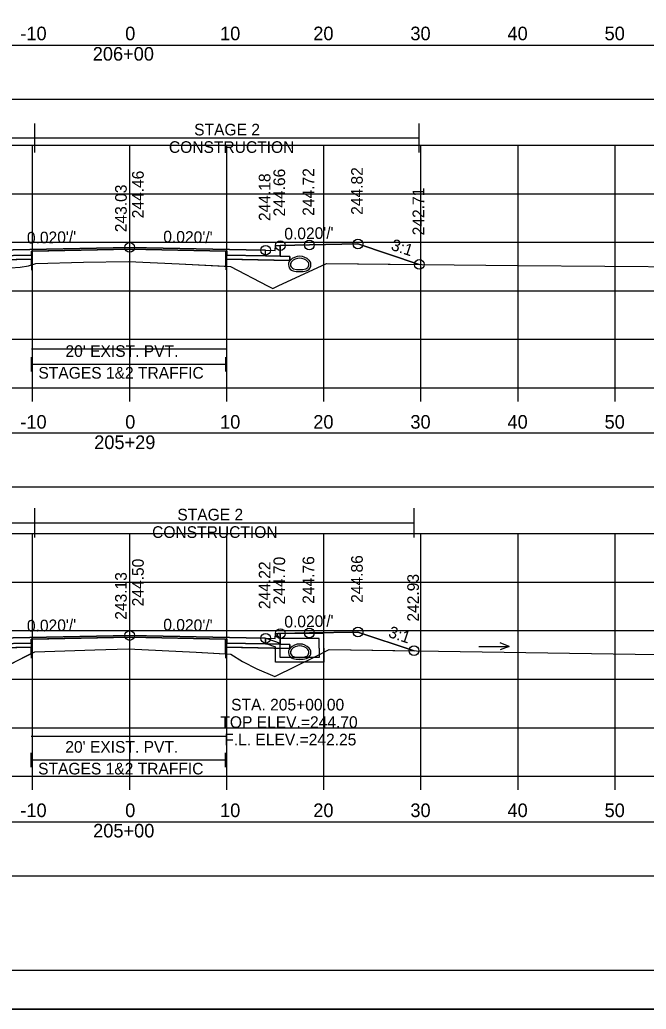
# Model space of a CAD drawing. Extents: x 1369627 to 1374022, y 380035 to 398173.
# Drawn here: x 1372087.2 to 1372151.7, y 381318.8 to 381420.7 of the extents above; entities that cross this region are included whole.
import ezdxf

# ---------------------------------------------------------------- set-up
doc = ezdxf.new("R2010")
doc.units = 0
for name, color, linetype in [('Default', 7, 'Continuous'), ('R_Alt Surface', 7, 'Continuous'), ('R_Axis', 7, 'Continuous'), ('R_Axis Annot', 7, 'Continuous'), ('R_Border', 7, 'Continuous'), ('R_Drive', 7, 'Continuous'), ('R_Exist Surface', 7, 'Continuous'), ('R_Fin Surface', 7, 'Continuous'), ('R_Grid', 7, 'Continuous'), ('R_MOT', 7, 'Continuous'), ('R_No Plot', 7, 'Continuous'), ('R_Water', 7, 'Continuous'), ('R_Water Annot', 7, 'Continuous'), ('R_Xsect Elev', 7, 'Continuous'), ('R_Xsect Slope', 7, 'Continuous'), ('T_Vehicle Path Rt', 7, 'Continuous')]:
    doc.layers.add(name, color=color, linetype=linetype)

msp = doc.modelspace()

# ---------------------------------------------------------------- linework, layer by layer
at = {"layer": 'Default'}
for p, q in [((1372088.42, 381384.47), (1372088.42, 381385.97)), ((1372108.42, 381384.47), (1372108.42, 381385.97)), ((1372088.42, 381385.22), (1372108.42, 381385.22)), ((1372088.39, 381343.72), (1372088.39, 381345.22)), ((1372108.39, 381343.72), (1372108.39, 381345.22)), ((1372088.39, 381344.47), (1372108.39, 381344.47))]:
    msp.add_line(p, q, dxfattribs=at)
for points in [[(1371948.53, 381412.52), (1372248.53, 381412.52), (1372248.53, 381418.04), (1371948.53, 381418.04)], [(1372113.53, 381396.95), (1372113.54, 381397.45), (1372114.04, 381397.45), (1372114.03, 381396.35), (1372112.53, 381396.38), (1372112.53, 381396.97)], [(1371948.53, 381372.61), (1372248.53, 381372.61), (1372248.53, 381378.13), (1371948.53, 381378.13)], [(1372113.53, 381356.99), (1372113.54, 381357.49), (1372114.04, 381357.49), (1372114.03, 381356.39), (1372112.53, 381356.42), (1372112.53, 381357.01)], [(1371948.53, 381332.54), (1372248.53, 381332.54), (1372248.53, 381338.06), (1371948.53, 381338.06)]]:
    msp.add_lwpolyline(points, close=True, dxfattribs=at)
at = {"layer": 'R_Alt Surface'}
for points in [[(1372083.03, 381397.45), (1372083.03, 381396.35), (1372084.53, 381396.38), (1372088.42, 381396.46), (1372088.42, 381396.88), (1372098.53, 381397.08), (1372108.42, 381396.88), (1372108.42, 381396.46), (1372112.53, 381396.38), (1372114.03, 381396.35), (1372114.03, 381397.45)], [(1372083.03, 381357.49), (1372083.03, 381356.39), (1372084.53, 381356.42), (1372088.39, 381356.5), (1372088.39, 381356.91), (1372098.53, 381357.12), (1372108.39, 381356.92), (1372108.39, 381356.5), (1372112.53, 381356.42), (1372114.03, 381356.39), (1372114.03, 381357.49)]]:
    msp.add_lwpolyline(points, dxfattribs=at)
for points in [[(1372082.03, 381396.33), (1372083.03, 381396.35), (1372084.53, 381396.38), (1372088.42, 381396.46), (1372088.42, 381396.04), (1372082.03, 381395.92)], [(1372115.03, 381396.33), (1372114.03, 381396.35), (1372112.53, 381396.38), (1372108.42, 381396.46), (1372108.42, 381396.05), (1372115.03, 381395.92)], [(1372082.03, 381356.37), (1372083.03, 381356.39), (1372084.53, 381356.42), (1372088.39, 381356.5), (1372088.39, 381356.08), (1372082.03, 381355.95)], [(1372115.03, 381356.37), (1372114.03, 381356.39), (1372112.53, 381356.42), (1372108.39, 381356.5), (1372108.39, 381356.09), (1372115.03, 381355.95)]]:
    msp.add_lwpolyline(points, close=True, dxfattribs=at)
at = {"layer": 'R_Axis'}
for p, q in [((1371948.53, 381382.79), (1372248.53, 381382.79)), ((1372088.53, 381381.39), (1372088.53, 381382.79)), ((1372098.53, 381381.39), (1372098.53, 381382.79)), ((1372108.53, 381381.39), (1372108.53, 381382.79)), ((1372118.53, 381381.39), (1372118.53, 381382.79)), ((1372128.53, 381381.39), (1372128.53, 381382.79)), ((1372138.53, 381381.39), (1372138.53, 381382.79)), ((1372148.53, 381381.39), (1372148.53, 381382.79)), ((1371948.53, 381342.79), (1372248.53, 381342.79)), ((1372088.53, 381341.39), (1372088.53, 381342.79)), ((1372098.53, 381341.39), (1372098.53, 381342.79)), ((1372108.53, 381341.39), (1372108.53, 381342.79)), ((1372118.53, 381341.39), (1372118.53, 381342.79)), ((1372128.53, 381341.39), (1372128.53, 381342.79)), ((1372138.53, 381341.39), (1372138.53, 381342.79)), ((1372148.53, 381341.39), (1372148.53, 381342.79))]:
    msp.add_line(p, q, dxfattribs=at)
at = {"layer": 'R_Border'}
msp.add_line((1372256.71, 381322.79), (1371940.53, 381322.79), dxfattribs=at)
at = {"layer": 'R_Drive'}
for centre, radius, start, end in [((1372116.04, 381394.99), 1.35, 43.6485, 136.3515), ((1372116.04, 381394.99), 1.15, 43.6485, 136.3515), ((1372115.53, 381395.48), 0.646, 136.3515, 253.9529), ((1372115.53, 381395.48), 0.438, 136.3515, 253.9529), ((1372116.04, 381397.26), 2.29, 253.9529, 286.0471), ((1372116.55, 381395.48), 0.438, 286.0471, 43.6485), ((1372116.55, 381395.48), 0.646, 286.0471, 43.6485), ((1372116.04, 381397.26), 2.5, 253.9529, 286.0471), ((1372116.04, 381355.06), 1.35, 43.6485, 136.3515), ((1372115.53, 381355.55), 0.646, 136.3515, 253.9529), ((1372115.53, 381355.55), 0.438, 136.3515, 253.9529), ((1372116.04, 381355.06), 1.15, 43.6485, 136.3515), ((1372116.55, 381355.55), 0.438, 286.0471, 43.6485), ((1372116.55, 381355.55), 0.646, 286.0471, 43.6485), ((1372116.04, 381357.34), 2.5, 253.9529, 286.0471), ((1372116.04, 381357.34), 2.29, 253.9529, 286.0471)]:
    msp.add_arc(centre, radius, start, end, dxfattribs=at)
at = {"layer": 'R_Exist Surface'}
for points in [[(1372040.3, 381395.61), (1372056.57, 381395.35), (1372059.67, 381395.37), (1372066.45, 381395.38), (1372071.93, 381395.29), (1372079.34, 381395.18), (1372079.71, 381395.18), (1372081.29, 381395.14), (1372082.62, 381395.13), (1372084.79, 381395.15), (1372086.27, 381395.16), (1372087.24, 381395.23), (1372088.1, 381395.36), (1372088.88, 381395.61), (1372093.79, 381395.73), (1372098.42, 381395.82), (1372103.62, 381395.55), (1372108.93, 381395.29), (1372112.73, 381393.31), (1372113.27, 381393.03), (1372113.82, 381393.29), (1372118.8, 381395.61), (1372138.5, 381395.39), (1372156.43, 381395.24)], [(1372040.77, 381355.46), (1372046.93, 381355.54), (1372048.51, 381355.53), (1372056.33, 381355.65), (1372056.69, 381355.64), (1372058.03, 381355.64), (1372065.84, 381355.66), (1372067.69, 381355.62), (1372076.28, 381355.21), (1372082.77, 381353.28), (1372083.65, 381353.02), (1372084.66, 381353.55), (1372088.75, 381355.62), (1372094.94, 381355.83), (1372098.39, 381355.92), (1372105.39, 381355.56), (1372108.94, 381355.38), (1372110.15, 381354.6), (1372111.61, 381353.86), (1372113.48, 381353.07), (1372117.72, 381355.16), (1372119.07, 381355.86), (1372150.59, 381355.36), (1372156.58, 381355.27)]]:
    msp.add_lwpolyline(points, dxfattribs=at)
at = {"layer": 'R_Fin Surface'}
for points in [[(1372068.24, 381395.35), (1372075.02, 381397.61), (1372080.02, 381397.51), (1372083.02, 381397.45), (1372083.52, 381397.45), (1372083.53, 381396.95), (1372084.53, 381396.97), (1372086.53, 381397.01), (1372098.53, 381397.25), (1372110.53, 381397.01), (1372112.53, 381396.97), (1372113.53, 381396.95), (1372113.54, 381397.45), (1372114.04, 381397.45), (1372117.04, 381397.51), (1372122.04, 381397.61), (1372128.36, 381395.5)], [(1372068.78, 381355.57), (1372075.02, 381357.65), (1372080.02, 381357.55), (1372083.02, 381357.49), (1372083.52, 381357.49), (1372083.53, 381356.99), (1372084.53, 381357.01), (1372086.53, 381357.05), (1372098.53, 381357.29), (1372110.53, 381357.05), (1372112.53, 381357.01), (1372113.53, 381356.99), (1372113.54, 381357.49), (1372114.04, 381357.49), (1372117.04, 381357.55), (1372122.04, 381357.65), (1372127.82, 381355.72)]]:
    msp.add_lwpolyline(points, dxfattribs=at)
at = {"layer": 'R_Grid'}
for p, q in [((1371948.53, 381407.79), (1372248.53, 381407.79)), ((1372088.53, 381382.79), (1372088.53, 381407.79)), ((1372098.53, 381382.79), (1372098.53, 381407.79)), ((1372108.53, 381382.79), (1372108.53, 381407.79)), ((1372118.53, 381382.79), (1372118.53, 381407.79)), ((1372128.53, 381382.79), (1372128.53, 381407.79)), ((1372138.53, 381382.79), (1372138.53, 381407.79)), ((1372148.53, 381382.79), (1372148.53, 381407.79)), ((1371948.53, 381402.79), (1372248.53, 381402.79)), ((1371948.53, 381397.79), (1372248.53, 381397.79)), ((1371948.53, 381392.79), (1372248.53, 381392.79)), ((1371948.53, 381387.79), (1372248.53, 381387.79)), ((1371948.53, 381382.79), (1372248.53, 381382.79)), ((1371948.53, 381367.79), (1372248.53, 381367.79)), ((1372088.53, 381342.79), (1372088.53, 381367.79)), ((1372098.53, 381342.79), (1372098.53, 381367.79)), ((1372108.53, 381342.79), (1372108.53, 381367.79)), ((1372118.53, 381342.79), (1372118.53, 381367.79)), ((1372128.53, 381342.79), (1372128.53, 381367.79)), ((1372138.53, 381342.79), (1372138.53, 381367.79)), ((1372148.53, 381342.79), (1372148.53, 381367.79)), ((1371948.53, 381362.79), (1372248.53, 381362.79)), ((1371948.53, 381357.79), (1372248.53, 381357.79)), ((1371948.53, 381352.79), (1372248.53, 381352.79)), ((1371948.53, 381347.79), (1372248.53, 381347.79)), ((1371948.53, 381342.79), (1372248.53, 381342.79))]:
    msp.add_line(p, q, dxfattribs=at)
at = {"layer": 'R_MOT'}
for p, q in [((1372088.75, 381407.03), (1372088.75, 381410.03)), ((1372128.36, 381407.03), (1372128.36, 381410.03)), ((1372044.52, 381408.53), (1372128.36, 381408.53)), ((1372088.75, 381367.39), (1372088.75, 381370.39)), ((1372127.82, 381367.39), (1372127.82, 381370.39)), ((1372068.78, 381368.89), (1372127.82, 381368.89))]:
    msp.add_line(p, q, dxfattribs=at)
at = {"layer": 'R_No Plot'}
msp.add_line((1371928.13, 381318.81), (1372261.46, 381318.81), dxfattribs=at)
for points in [[(1371928.12, 381532.14), (1372261.46, 381532.14), (1372261.46, 381318.8), (1371928.12, 381318.8)], [(1372174.45, 381528.25), (1372194.07, 381528.25), (1372194.07, 381518.37), (1372210.18, 381518.37), (1372233.38, 381518.37), (1372233.38, 381485.7), (1372256.59, 381485.7), (1372256.71, 381322.79), (1371940.53, 381322.79), (1371940.53, 381528.25)], [(1372098.53, 381397.25), (1372086.53, 381397.01), (1372084.53, 381396.97), (1372084.53, 381396.38), (1372088.53, 381396.46), (1372088.53, 381396.88), (1372098.53, 381397.08), (1372108.53, 381396.88), (1372108.53, 381396.46), (1372112.53, 381396.38), (1372112.53, 381396.97), (1372110.53, 381397.01)], [(1372088.53, 381396.46), (1372084.53, 381396.38), (1372083.03, 381396.35), (1372082.03, 381396.33), (1372082.03, 381395.91), (1372088.53, 381396.04)], [(1372108.53, 381396.46), (1372112.53, 381396.38), (1372114.03, 381396.35), (1372115.03, 381396.33), (1372115.03, 381395.91), (1372108.53, 381396.04)], [(1372088.53, 381356.5), (1372084.53, 381356.42), (1372083.03, 381356.39), (1372082.03, 381356.37), (1372082.03, 381355.95), (1372088.53, 381356.08)], [(1372098.53, 381357.29), (1372086.53, 381357.05), (1372084.53, 381357.01), (1372084.53, 381356.42), (1372088.53, 381356.5), (1372088.53, 381356.92), (1372098.53, 381357.12), (1372108.53, 381356.92), (1372108.53, 381356.5), (1372112.53, 381356.42), (1372112.53, 381357.01), (1372110.53, 381357.05)], [(1372108.53, 381356.5), (1372112.53, 381356.42), (1372114.03, 381356.39), (1372115.03, 381356.37), (1372115.03, 381355.95), (1372108.53, 381356.08)]]:
    msp.add_lwpolyline(points, close=True, dxfattribs=at)
for points in [[(1372083.02, 381397.45), (1372083.03, 381396.35), (1372084.53, 381396.38), (1372088.53, 381396.46), (1372088.53, 381396.88), (1372098.53, 381397.08), (1372108.53, 381396.88), (1372108.53, 381396.46), (1372112.53, 381396.38), (1372114.03, 381396.35), (1372114.04, 381397.45)], [(1372088.42, 381386.82), (1372108.42, 381386.82)], [(1372083.02, 381357.49), (1372083.03, 381356.39), (1372084.53, 381356.42), (1372088.53, 381356.5), (1372088.53, 381356.92), (1372098.53, 381357.12), (1372108.53, 381356.92), (1372108.53, 381356.5), (1372112.53, 381356.42), (1372114.03, 381356.39), (1372114.04, 381357.49)], [(1372088.39, 381346.92), (1372108.39, 381346.92)]]:
    msp.add_lwpolyline(points, dxfattribs=at)
for centre in [(1372122.04, 381397.61), (1372098.53, 381397.25), (1372112.53, 381396.97), (1372114.04, 381397.45), (1372117.04, 381397.51), (1372128.36, 381395.5), (1372098.53, 381357.29), (1372112.53, 381357.01), (1372114.04, 381357.49), (1372117.04, 381357.55), (1372122.04, 381357.65), (1372127.82, 381355.72)]:
    msp.add_circle(centre, 0.5, dxfattribs=at)
at = {"layer": 'R_Water'}
for p, q in [((1372113.71, 381357.32), (1372113.79, 381357.49)), ((1372118.54, 381357.49), (1372113.79, 381357.49)), ((1372118.54, 381355.99), (1372118.54, 381357.49)), ((1372112.54, 381357.01), (1372114.04, 381356.49)), ((1372112.54, 381356.48), (1372113.54, 381356.13)), ((1372113.71, 381357.32), (1372114.04, 381356.99)), ((1372118.04, 381356.99), (1372114.04, 381356.99)), ((1372114.04, 381355.99), (1372114.04, 381356.49)), ((1372118.04, 381355.99), (1372118.04, 381356.99)), ((1372113.54, 381355.99), (1372113.54, 381356.13))]:
    msp.add_line(p, q, dxfattribs=at)
for points in [[(1372112.54, 381356.48), (1372112.54, 381357.01)], [(1372118.54, 381355.99), (1372118.54, 381354.54), (1372116.04, 381354.54), (1372113.54, 381354.54), (1372113.54, 381355.99)], [(1372118.04, 381355.99), (1372118.04, 381355.04), (1372116.04, 381355.04), (1372114.04, 381355.04), (1372114.04, 381355.99)]]:
    msp.add_lwpolyline(points, dxfattribs=at)
at = {"layer": 'R_Water Annot'}
for p, q in [((1372137.63, 381356.17), (1372136.67, 381356.52)), ((1372134.49, 381356.17), (1372137.63, 381356.17)), ((1372137.63, 381356.17), (1372136.67, 381355.82))]:
    msp.add_line(p, q, dxfattribs=at)
for centre, radius, start, end in [((1372116.04, 381355.06), 1.35, 43.6485, 136.3515), ((1372115.53, 381355.55), 0.646, 136.3515, 253.9529), ((1372115.53, 381355.55), 0.438, 136.3515, 253.9529), ((1372116.04, 381355.06), 1.15, 43.6485, 136.3515), ((1372116.55, 381355.55), 0.438, 286.0471, 43.6485), ((1372116.55, 381355.55), 0.646, 286.0471, 43.6485), ((1372116.04, 381357.33), 2.5, 253.9529, 286.0471), ((1372116.04, 381357.33), 2.29, 253.9529, 286.0471)]:
    msp.add_arc(centre, radius, start, end, dxfattribs=at)
at = {"layer": 'R_Xsect Elev'}
for p, q in [((1372098.53, 381395.82), (1372098.53, 381405.82)), ((1372098.53, 381355.91), (1372098.53, 381365.91))]:
    msp.add_line(p, q, dxfattribs=at)
at = {"layer": 'T_Vehicle Path Rt'}
for p, q in [((1372114.04, 381397.45), (1372114.03, 381396.35)), ((1372088.42, 381396.46), (1372088.42, 381396.04)), ((1372108.42, 381396.05), (1372108.42, 381396.46)), ((1372088.42, 381396.04), (1372088.42, 381394.92)), ((1372088.42, 381396.04), (1372088.42, 381395.46)), ((1372088.42, 381395.46), (1372088.42, 381396.04)), ((1372108.42, 381396.05), (1372108.42, 381394.93)), ((1372108.42, 381395.32), (1372108.42, 381396.05)), ((1372108.42, 381396.05), (1372108.42, 381395.32)), ((1372108.42, 381395.32), (1372108.93, 381395.29)), ((1372114.04, 381357.49), (1372114.03, 381356.39)), ((1372088.39, 381356.5), (1372088.39, 381356.08)), ((1372108.39, 381356.09), (1372108.39, 381356.5)), ((1372088.39, 381356.08), (1372088.39, 381354.96)), ((1372088.39, 381355.44), (1372088.39, 381356.08)), ((1372088.39, 381356.08), (1372088.39, 381355.44)), ((1372108.39, 381356.09), (1372108.39, 381354.97)), ((1372108.39, 381356.09), (1372108.39, 381355.41)), ((1372108.39, 381355.41), (1372108.39, 381356.09)), ((1372108.39, 381355.41), (1372108.94, 381355.38))]:
    msp.add_line(p, q, dxfattribs=at)
for points in [[(1372128.36, 381395.5), (1372122.04, 381397.61), (1372117.04, 381397.51), (1372114.04, 381397.45)], [(1372088.42, 381396.04), (1372082.03, 381395.92), (1372082.03, 381396.33), (1372083.03, 381396.35)], [(1372108.42, 381396.46), (1372108.42, 381396.88), (1372098.53, 381397.08), (1372088.42, 381396.88), (1372088.42, 381396.46)], [(1372114.03, 381396.35), (1372115.03, 381396.33), (1372115.03, 381395.92), (1372108.42, 381396.05)], [(1372068.24, 381395.35), (1372071.93, 381395.29), (1372079.34, 381395.18), (1372079.71, 381395.18), (1372081.29, 381395.14), (1372082.62, 381395.13), (1372084.79, 381395.15), (1372086.27, 381395.16), (1372087.24, 381395.23), (1372088.1, 381395.36), (1372088.42, 381395.46)], [(1372088.42, 381395.46), (1372088.88, 381395.61), (1372093.79, 381395.73), (1372098.42, 381395.82), (1372103.62, 381395.55), (1372108.42, 381395.32)], [(1372108.93, 381395.29), (1372112.73, 381393.31), (1372113.27, 381393.03), (1372113.82, 381393.29), (1372118.8, 381395.61), (1372128.36, 381395.5)], [(1372127.82, 381355.72), (1372122.04, 381357.65), (1372117.04, 381357.55), (1372114.04, 381357.49)], [(1372088.39, 381356.08), (1372082.03, 381355.95), (1372082.03, 381356.37), (1372083.03, 381356.39)], [(1372108.39, 381356.5), (1372108.39, 381356.92), (1372098.53, 381357.12), (1372088.39, 381356.91), (1372088.39, 381356.5)], [(1372114.03, 381356.39), (1372115.03, 381356.37), (1372115.03, 381355.95), (1372108.39, 381356.09)], [(1372068.78, 381355.57), (1372076.28, 381355.21), (1372082.77, 381353.28), (1372083.65, 381353.02), (1372084.66, 381353.55), (1372088.39, 381355.44)], [(1372088.39, 381355.44), (1372088.75, 381355.62), (1372094.94, 381355.83), (1372098.39, 381355.92), (1372105.39, 381355.56), (1372108.39, 381355.41)], [(1372108.94, 381355.38), (1372110.15, 381354.6), (1372111.61, 381353.86), (1372113.48, 381353.07), (1372117.72, 381355.16), (1372119.07, 381355.86), (1372127.82, 381355.72)]]:
    msp.add_lwpolyline(points, dxfattribs=at)

# ---------------------------------------------------------------- texts
at = {"layer": 'R_Axis Annot'}
for s, height, p in [('-10', 1.4, (1372087.27, 381418.59)), ('0', 1.4, (1372098.07, 381418.59)), ('10', 1.4, (1372107.84, 381418.59)), ('20', 1.4, (1372117.44, 381418.59)), ('30', 1.4, (1372127.44, 381418.59)), ('40', 1.4, (1372137.44, 381418.59)), ('50', 1.4, (1372147.44, 381418.59)), ('206+00', 1.4, (1372094.73, 381416.49)), ("20' EXIST. PVT.", 1.2, (1372091.92, 381385.98)), ('STAGES 1&2 TRAFFIC', 1.2, (1372089.13, 381383.74)), ('-10', 1.4, (1372087.27, 381378.59)), ('0', 1.4, (1372098.07, 381378.59)), ('10', 1.4, (1372107.84, 381378.59)), ('20', 1.4, (1372117.44, 381378.59)), ('30', 1.4, (1372127.44, 381378.59)), ('40', 1.4, (1372137.44, 381378.59)), ('50', 1.4, (1372147.44, 381378.59)), ('205+29', 1.4, (1372094.88, 381376.49)), ("20' EXIST. PVT.", 1.2, (1372091.9, 381345.22)), ('STAGES 1&2 TRAFFIC', 1.2, (1372089.1, 381342.98)), ('-10', 1.4, (1372087.27, 381338.59)), ('0', 1.4, (1372098.07, 381338.59)), ('10', 1.4, (1372107.84, 381338.59)), ('20', 1.4, (1372117.44, 381338.59)), ('30', 1.4, (1372127.44, 381338.59)), ('40', 1.4, (1372137.44, 381338.59)), ('50', 1.4, (1372147.44, 381338.59)), ('205+00', 1.4, (1372094.77, 381336.49))]:
    msp.add_text(s, height=height, dxfattribs=at).set_placement(p)
at = {"layer": 'R_MOT'}
for s, p in [('STAGE 2', (1372105.17, 381408.79)), ('CONSTRUCTION', (1372102.57, 381406.99)), ('STAGE 2', (1372103.44, 381369.14)), ('CONSTRUCTION', (1372100.84, 381367.34))]:
    msp.add_text(s, height=1.2, dxfattribs=at).set_placement(p)
at = {"layer": 'R_Water Annot'}
for s, p in [('STA. 205+00.00', (1372108.98, 381349.57)), ('TOP ELEV.=244.70', (1372107.87, 381347.77)), ('F.L. ELEV.=242.25', (1372108.27, 381345.97))]:
    msp.add_text(s, height=1.2, dxfattribs=at).set_placement(p)
at = {"layer": 'R_Xsect Elev'}
for s, p in [('244.66', (1372114.54, 381400.45)), ('244.72', (1372117.54, 381400.51)), ('244.82', (1372122.54, 381400.61)), ('244.46', (1372099.98, 381400.25)), ('244.18', (1372113.03, 381399.97)), ('243.03', (1372098.23, 381398.82)), ('242.71', (1372128.86, 381398.5)), ('244.50', (1372099.98, 381360.29)), ('244.22', (1372113.03, 381360.01)), ('244.70', (1372114.54, 381360.49)), ('244.76', (1372117.54, 381360.55)), ('244.86', (1372122.54, 381360.65)), ('243.13', (1372098.23, 381358.91)), ('242.93', (1372128.32, 381358.72))]:
    msp.add_text(s, height=1.2, rotation=90, dxfattribs=at).set_placement(p)
at = {"layer": 'R_Xsect Slope'}
for s, rotation, p in [("0.020'/'", 1.1458, (1372114.47, 381398.06)), ("0.020'/'", 1.1458, (1372087.96, 381397.64)), ("0.020'/'", 358.8542, (1372101.98, 381397.78)), ('3:1', 341.5668, (1372125.36, 381397.03)), ("0.020'/'", 1.1458, (1372114.47, 381358.1)), ("0.020'/'", 1.1458, (1372087.96, 381357.68)), ("0.020'/'", 358.8542, (1372101.98, 381357.82)), ('3:1', 341.5668, (1372125.09, 381357.16))]:
    msp.add_text(s, height=1.2, rotation=rotation, dxfattribs=at).set_placement(p)

doc.saveas('drawing.dxf')
